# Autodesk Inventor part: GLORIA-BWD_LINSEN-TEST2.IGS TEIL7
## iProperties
Created: 2005-04
Part Number: GLORIA-BWD_LINSEN-TEST2.IGS TEIL7
Document SubType Name: Modeling
Designer: Nordmeyer
Manufacturer: Standard
Standards Organization: Custom
Author: Nordmeyer
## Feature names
1. Erst1
